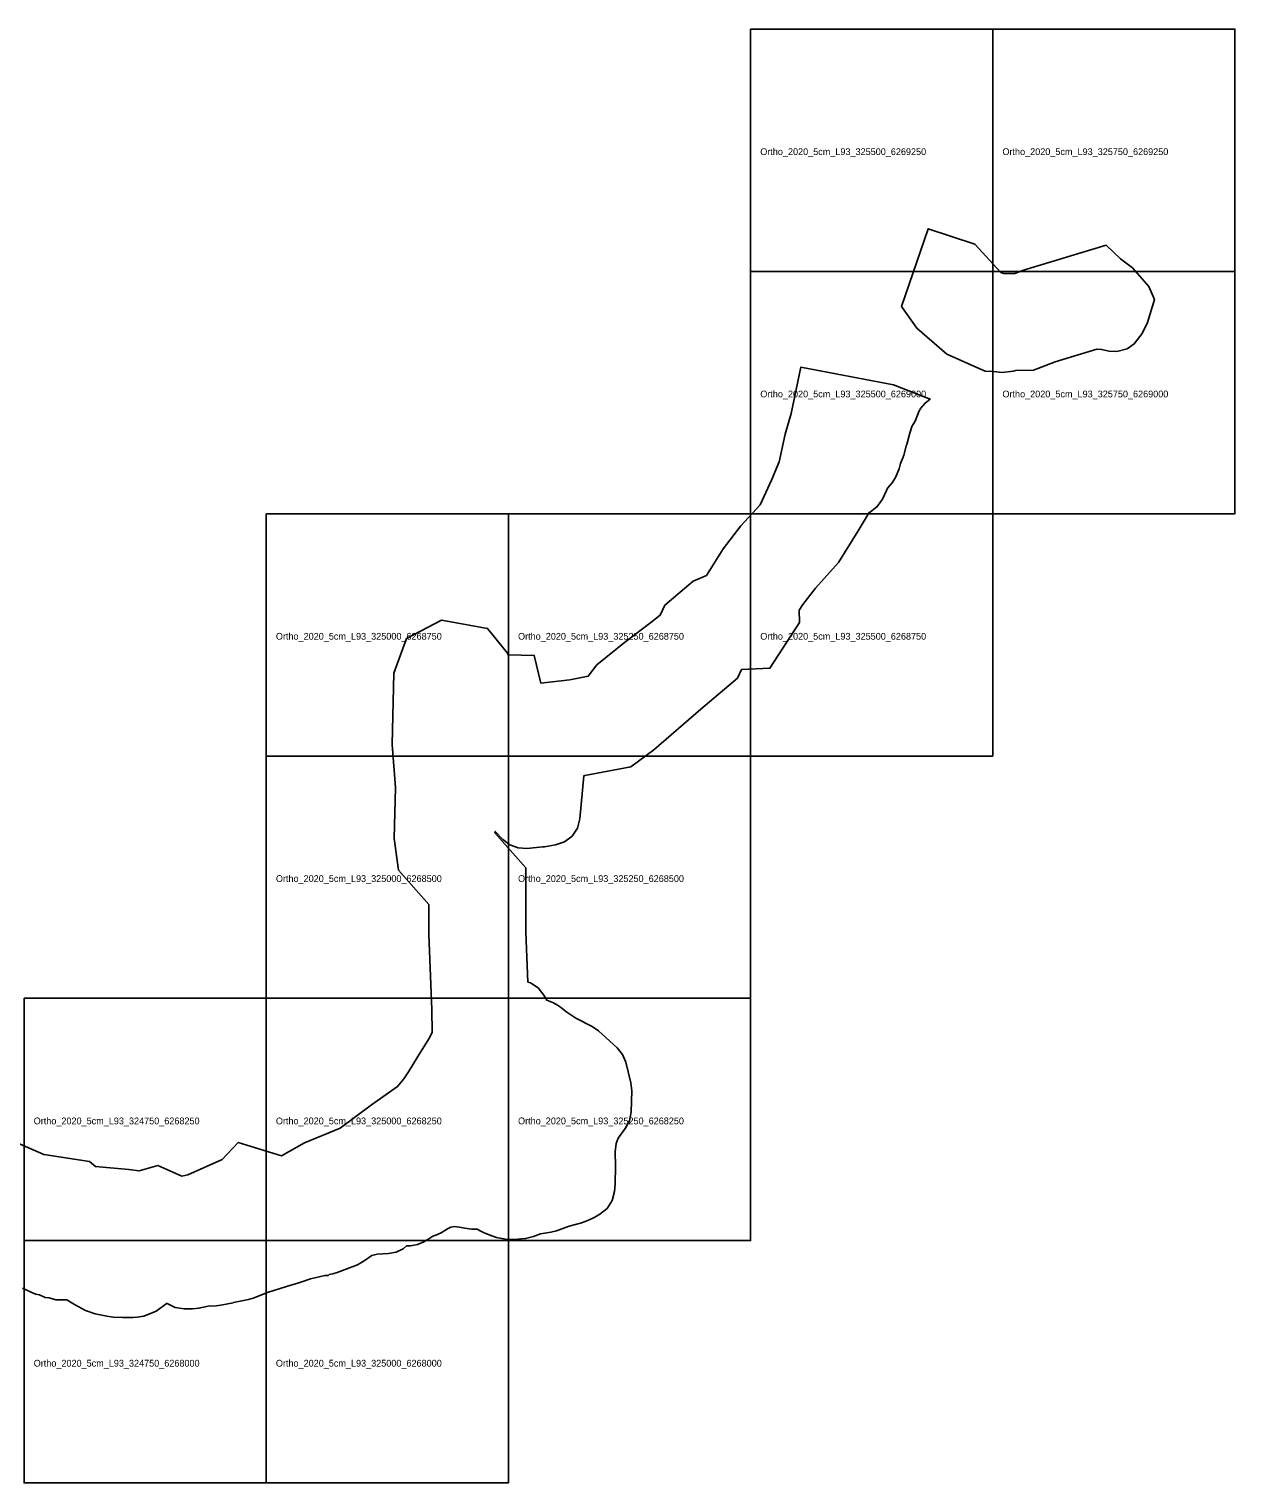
# Model space of a CAD drawing. Extents: x 322000 to 326000, y 6266750 to 6269250.
# Drawn here: x 324755 to 326000, y 6267750 to 6269250 of the extents above; entities that cross this region are included whole.
import ezdxf

# ---------------------------------------------------------------- set-up
doc = ezdxf.new("R2010")
doc.units = 0
for name, color, linetype in [('Ortho_footprint', 7, 'Continuous'), ('Ortho_name', 7, 'Continuous'), ('Perim', 7, 'Continuous')]:
    doc.layers.add(name, color=color, linetype=linetype)

msp = doc.modelspace()

# ---------------------------------------------------------------- linework, layer by layer
at = {"layer": 'Ortho_footprint'}
for points in [[(325500, 6269250), (325750, 6269250), (325750, 6269000), (325500, 6269000)], [(325750, 6269250), (326000, 6269250), (326000, 6269000), (325750, 6269000)], [(325500, 6269000), (325750, 6269000), (325750, 6268750), (325500, 6268750)], [(325750, 6269000), (326000, 6269000), (326000, 6268750), (325750, 6268750)], [(325000, 6268750), (325250, 6268750), (325250, 6268500), (325000, 6268500)], [(325250, 6268750), (325500, 6268750), (325500, 6268500), (325250, 6268500)], [(325500, 6268750), (325750, 6268750), (325750, 6268500), (325500, 6268500)], [(325000, 6268500), (325250, 6268500), (325250, 6268250), (325000, 6268250)], [(325250, 6268500), (325500, 6268500), (325500, 6268250), (325250, 6268250)], [(324750, 6268250), (325000, 6268250), (325000, 6268000), (324750, 6268000)], [(325000, 6268250), (325250, 6268250), (325250, 6268000), (325000, 6268000)], [(325250, 6268250), (325500, 6268250), (325500, 6268000), (325250, 6268000)], [(324750, 6268000), (325000, 6268000), (325000, 6267750), (324750, 6267750)], [(325000, 6268000), (325250, 6268000), (325250, 6267750), (325000, 6267750)]]:
    msp.add_lwpolyline(points, close=True, dxfattribs=at)
at = {"layer": 'Perim'}
msp.add_lwpolyline([(325671.7, 6268941.5), (325655.9, 6268963.6), (325683.4, 6269044), (325731.5, 6269028), (325758.3, 6268999), (325761.5, 6268997.7), (325772.7, 6268997.9), (325781.9, 6269001.3), (325867, 6269027.2), (325881.8, 6269013), (325894.3, 6269003.5), (325911, 6268984.5), (325916.9, 6268971.1), (325909.8, 6268947.2), (325904.4, 6268935.9), (325896, 6268925.1), (325888.6, 6268920), (325878, 6268917.3), (325870.3, 6268917.6), (325862.4, 6268919.5), (325857.5, 6268919.7), (325814.3, 6268906.7), (325792.1, 6268898.1), (325773.8, 6268897.8), (325771.2, 6268897), (325759.7, 6268895.8), (325750.9, 6268896.6), (325742.2, 6268897.1), (325702.6, 6268914.7)], close=True, dxfattribs=at)
msp.add_lwpolyline([(324748.4, 6267951.1), (324762, 6267944.9), (324766, 6267943.9), (324771.8, 6267941.2), (324776, 6267940.9), (324783, 6267939), (324794.2, 6267939), (324802.1, 6267934.2), (324813.5, 6267928), (324823.5, 6267924.3), (324835.4, 6267922.2), (324842.1, 6267921), (324851.7, 6267920.7), (324853, 6267920.7), (324862.2, 6267920.7), (324866.8, 6267921), (324873.8, 6267922.1), (324886.5, 6267927.3), (324897.7, 6267935.3), (324897.9, 6267935), (324906.2, 6267930.9), (324915.3, 6267929.5), (324923.8, 6267929.5), (324930.6, 6267930.3), (324940.2, 6267932.5), (324948.2, 6267932.8), (324953.1, 6267933.4), (324966, 6267935.9), (324966.4, 6267936), (324981.8, 6267939.3), (324986.5, 6267940.7), (325001.2, 6267946.6), (325021.1, 6267952.7), (325033.6, 6267956.3), (325035.9, 6267957.1), (325045.6, 6267960.7), (325060.6, 6267964), (325064, 6267963.9), (325065.1, 6267964.9), (325068.8, 6267965.7), (325073.3, 6267967.1), (325094.2, 6267975.1), (325101.3, 6267979), (325109.1, 6267984.8), (325114.6, 6267986.1), (325126.1, 6267986.6), (325134.1, 6267988), (325141.4, 6267991.5), (325144.8, 6267994.5), (325149, 6267994.7), (325156.2, 6267995.9), (325162.9, 6267998.8), (325168, 6268001.9), (325171.9, 6268004.7), (325175, 6268005.7), (325180.6, 6268008.2), (325187.3, 6268012), (325190.7, 6268014), (325194, 6268014.4), (325199.4, 6268014), (325205.2, 6268012.7), (325211.9, 6268011.9), (325217.7, 6268011.9), (325221.5, 6268009.8), (325224.3, 6268008.5), (325232, 6268005.2), (325237.9, 6268003.3), (325247.1, 6268001.5), (325255.7, 6268001), (325267.8, 6268002.1), (325276, 6268004.1), (325283.2, 6268006.9), (325293.9, 6268008.6), (325299.8, 6268010.2), (325312.8, 6268015), (325324.6, 6268017.9), (325330.3, 6268019.9), (325337.3, 6268023.2), (325339.3, 6268024.3), (325344.5, 6268027.2), (325351.9, 6268033.2), (325357.1, 6268041.3), (325359.5, 6268050.6), (325360.2, 6268058.6), (325360.3, 6268060.6), (325360.7, 6268074.9), (325360.7, 6268076.9), (325360.1, 6268091.6), (325361.4, 6268100.2), (325363.3, 6268105.7), (325370.7, 6268115.6), (325375.1, 6268123.7), (325376.7, 6268132.7), (325377.4, 6268154.5), (325376.5, 6268162.7), (325371.1, 6268184.1), (325367.8, 6268192.1), (325362.3, 6268198.9), (325343.2, 6268216.4), (325336.4, 6268221), (325319.5, 6268229.6), (325310.2, 6268235.7), (325303.8, 6268240.7), (325300.6, 6268242.9), (325296.5, 6268245.4), (325289.8, 6268248), (325286.7, 6268253.4), (325280.8, 6268260.9), (325272.8, 6268266.1), (325270.1, 6268266.8), (325268.1, 6268318.1), (325267.9, 6268384.6), (325236, 6268420.8), (325236.5, 6268422.2), (325244.4, 6268413.8), (325251.5, 6268408.2), (325260, 6268405.1), (325269.1, 6268404.6), (325285.5, 6268406.2), (325287.4, 6268406.4), (325298.8, 6268408.3), (325308.1, 6268411.4), (325315.9, 6268417.4), (325321.4, 6268425.6), (325323.8, 6268435.2), (325327.9, 6268479.7), (325328.9, 6268479.9), (325376.5, 6268488.7), (325400.1, 6268506.4), (325448.6, 6268548.2), (325486.5, 6268580.3), (325490.8, 6268589.2), (325520, 6268590.6), (325550.5, 6268637.6), (325550.2, 6268650.4), (325554, 6268656.4), (325566.9, 6268673.2), (325590.9, 6268699.6), (325611, 6268732.4), (325622.4, 6268751.1), (325623.4, 6268751.5), (325630.8, 6268757.3), (325636.1, 6268765), (325640.2, 6268773.8), (325641.2, 6268776.5), (325646.1, 6268782), (325649.5, 6268787.2), (325653.5, 6268796.4), (325654.8, 6268801.9), (325657.1, 6268807.6), (325658.1, 6268810.5), (325661.1, 6268821.2), (325661.2, 6268821.3), (325663.8, 6268830.8), (325666.6, 6268839.9), (325669.8, 6268845.3), (325672.4, 6268851.5), (325674.2, 6268856), (325675.7, 6268858.8), (325677.1, 6268860.5), (325677.7, 6268861.2), (325680.1, 6268864.1), (325685.5, 6268868.3), (325647.7, 6268883), (325551.9, 6268901.3), (325541.9, 6268853.3), (325535.6, 6268831.9), (325529.6, 6268803.4), (325521.6, 6268784.5), (325510, 6268759.3), (325490, 6268737.5), (325471.8, 6268713.7), (325454.5, 6268686.3), (325440.7, 6268680.3), (325411.6, 6268655.5), (325406.7, 6268645.3), (325396.9, 6268637.9), (325369.8, 6268617), (325341.2, 6268593.9), (325332.5, 6268582.3), (325313.4, 6268578.7), (325283.6, 6268575), (325276.7, 6268603.7), (325249.9, 6268604.5), (325249.1, 6268606), (325228.6, 6268631.6), (325180.9, 6268640.3), (325144.7, 6268621.2), (325131.9, 6268585.3), (325130, 6268511.7), (325133.5, 6268467.5), (325132, 6268415), (325136.6, 6268382.2), (325168, 6268346.7), (325168, 6268316), (325171.1, 6268238.4), (325171.2, 6268214.7), (325167.8, 6268208.1), (325156.6, 6268190.1), (325147, 6268174.3), (325142.1, 6268167), (325135.5, 6268159.1), (325108.7, 6268140.2), (325076.4, 6268116), (325039.6, 6268100.8), (325015.9, 6268087.6), (324971.2, 6268101.4), (324954.6, 6268083.6), (324919, 6268067.7), (324912.8, 6268066.4), (324888, 6268077.6), (324869, 6268071.9), (324858.1, 6268073.4), (324823.7, 6268076.4), (324817.6, 6268081.5), (324770.5, 6268088.9), (324715.6, 6268112.5)], dxfattribs=at)

# ---------------------------------------------------------------- texts
at = {"layer": 'Ortho_name'}
for s, p in [('Ortho_2020_5cm_L93_325500_6269250', (325510, 6269120)), ('Ortho_2020_5cm_L93_325750_6269250', (325760, 6269120)), ('Ortho_2020_5cm_L93_325500_6269000', (325510, 6268870)), ('Ortho_2020_5cm_L93_325750_6269000', (325760, 6268870)), ('Ortho_2020_5cm_L93_325000_6268750', (325010, 6268620)), ('Ortho_2020_5cm_L93_325250_6268750', (325260, 6268620)), ('Ortho_2020_5cm_L93_325500_6268750', (325510, 6268620)), ('Ortho_2020_5cm_L93_325000_6268500', (325010, 6268370)), ('Ortho_2020_5cm_L93_325250_6268500', (325260, 6268370)), ('Ortho_2020_5cm_L93_324750_6268250', (324760, 6268120)), ('Ortho_2020_5cm_L93_325000_6268250', (325010, 6268120)), ('Ortho_2020_5cm_L93_325250_6268250', (325260, 6268120)), ('Ortho_2020_5cm_L93_324750_6268000', (324760, 6267870)), ('Ortho_2020_5cm_L93_325000_6268000', (325010, 6267870))]:
    msp.add_text(s, height=7, dxfattribs=at).set_placement(p)

doc.saveas('drawing.dxf')
